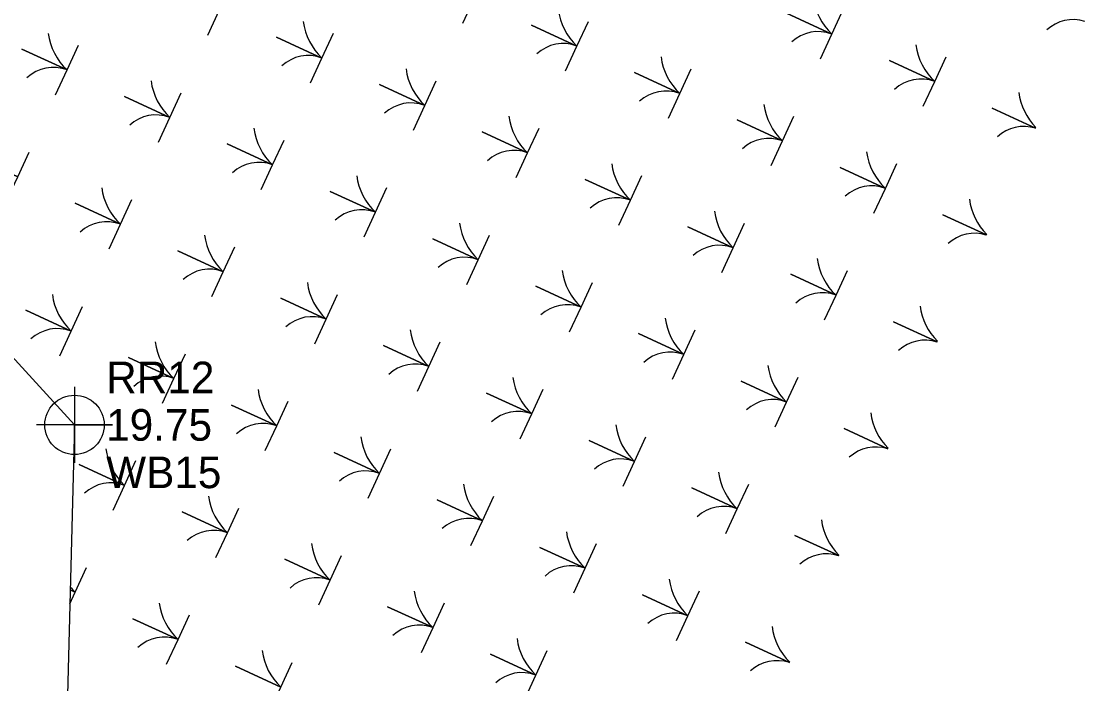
# Model space of a CAD drawing. Extents: x 2532037 to 2533565, y 713396 to 716867.
# Drawn here: x 2532898.3 to 2532982.3, y 715371.9 to 715424.3 of the extents above; entities that cross this region are included whole.
import ezdxf

# ---------------------------------------------------------------- set-up
doc = ezdxf.new("R2010")
doc.units = 0
for name, color, linetype in [('Exist Environmental Wetland Boundary', 7, 'Continuous'), ('Exist Environmental Wetland Boundary Cogo Comment', 7, 'Continuous'), ('Exist Environmental Wetland Boundary Cogo Elevation', 7, 'Continuous'), ('Exist Environmental Wetland Boundary Cogo Number', 7, 'Continuous'), ('Exist Environmental Wetland Boundary Cogo Point CELL', 7, 'Continuous'), ('Scratch_Level_1', 7, 'Continuous')]:
    doc.layers.add(name, color=color, linetype=linetype)

msp = doc.modelspace()

# ---------------------------------------------------------------- linework, layer by layer
at = {"layer": 'Exist Environmental Wetland Boundary'}
for p, q in [((2532882.006, 715414.844), (2532902.531, 715392.376)), ((2532902.531, 715392.376), (2532901.019, 715334.859))]:
    msp.add_line(p, q, dxfattribs=at)
at = {"layer": 'Exist Environmental Wetland Boundary Cogo Point CELL'}
msp.add_lwpolyline([(2532902.531, 715395.376), (2532902.531, 715389.376), (2532902.531, 715392.376), (2532905.531, 715392.376), (2532899.531, 715392.376)], dxfattribs=at)
msp.add_circle((2532902.531, 715392.376), 2.344, dxfattribs=at)
at = {"layer": 'Scratch_Level_1'}
for points in [[(2532933.199, 715424.118), (2532934.1, 715426.07), (2532930.519, 715427.724), (2532934.1, 715426.07), (2532935.002, 715428.023)], [(2532913.058, 715423.172), (2532913.959, 715425.125), (2532910.377, 715426.778), (2532913.959, 715425.125), (2532914.86, 715427.077)], [(2532961.462, 715421.314), (2532962.363, 715423.267), (2532958.781, 715424.92), (2532962.363, 715423.267), (2532963.265, 715425.219)], [(2532941.321, 715420.369), (2532942.222, 715422.321), (2532938.64, 715423.975), (2532942.222, 715422.321), (2532943.123, 715424.273)], [(2532921.179, 715419.423), (2532922.081, 715421.375), (2532918.499, 715423.029), (2532922.081, 715421.375), (2532922.982, 715423.328)], [(2532901.038, 715418.477), (2532901.939, 715420.43), (2532898.357, 715422.083), (2532901.939, 715420.43), (2532902.841, 715422.382)], [(2532969.583, 715417.565), (2532970.485, 715419.517), (2532966.903, 715421.171), (2532970.485, 715419.517), (2532971.386, 715421.47)], [(2532949.442, 715416.619), (2532950.343, 715418.572), (2532946.761, 715420.225), (2532950.343, 715418.572), (2532951.245, 715420.524)], [(2532929.301, 715415.674), (2532930.202, 715417.626), (2532926.62, 715419.28), (2532930.202, 715417.626), (2532931.103, 715419.578)], [(2532909.159, 715414.728), (2532910.061, 715416.68), (2532906.479, 715418.334), (2532910.061, 715416.68), (2532910.962, 715418.633)], [(2532978.455, 715415.838), (2532975.024, 715417.421), (2532978.455, 715415.838)], [(2532957.563, 715412.87), (2532958.465, 715414.822), (2532954.883, 715416.476), (2532958.465, 715414.822), (2532959.366, 715416.775)], [(2532937.422, 715411.924), (2532938.323, 715413.877), (2532934.742, 715415.53), (2532938.323, 715413.877), (2532939.225, 715415.829)], [(2532917.281, 715410.979), (2532918.182, 715412.931), (2532914.6, 715414.585), (2532918.182, 715412.931), (2532919.083, 715414.883)], [(2532897.139, 715410.033), (2532898.041, 715411.985), (2532894.459, 715413.639), (2532898.041, 715411.985), (2532898.942, 715413.938)], [(2532965.685, 715409.12), (2532966.586, 715411.073), (2532963.004, 715412.726), (2532966.586, 715411.073), (2532967.488, 715413.025)], [(2532945.544, 715408.175), (2532946.445, 715410.127), (2532942.863, 715411.781), (2532946.445, 715410.127), (2532947.346, 715412.08)], [(2532925.402, 715407.229), (2532926.304, 715409.182), (2532922.722, 715410.835), (2532926.304, 715409.182), (2532927.205, 715411.134)], [(2532905.261, 715406.284), (2532906.162, 715408.236), (2532902.58, 715409.89), (2532906.162, 715408.236), (2532907.064, 715410.188)], [(2532974.567, 715407.389), (2532971.126, 715408.977), (2532974.567, 715407.389)], [(2532953.665, 715404.425), (2532954.566, 715406.378), (2532950.984, 715408.031), (2532954.566, 715406.378), (2532955.468, 715408.33)], [(2532933.524, 715403.48), (2532934.425, 715405.432), (2532930.843, 715407.086), (2532934.425, 715405.432), (2532935.326, 715407.385)], [(2532913.382, 715402.534), (2532914.284, 715404.487), (2532910.702, 715406.14), (2532914.284, 715404.487), (2532915.185, 715406.439)], [(2532961.786, 715400.676), (2532962.688, 715402.628), (2532959.106, 715404.282), (2532962.688, 715402.628), (2532963.589, 715404.581)], [(2532941.645, 715399.73), (2532942.546, 715401.683), (2532938.965, 715403.336), (2532942.546, 715401.683), (2532943.448, 715403.635)], [(2532921.504, 715398.785), (2532922.405, 715400.737), (2532918.823, 715402.391), (2532922.405, 715400.737), (2532923.306, 715402.69)], [(2532901.362, 715397.839), (2532902.264, 715399.792), (2532898.682, 715401.445), (2532902.264, 715399.792), (2532903.165, 715401.744)], [(2532970.678, 715398.94), (2532967.227, 715400.533), (2532970.678, 715398.94)], [(2532949.767, 715395.981), (2532950.668, 715397.933), (2532947.086, 715399.587), (2532950.668, 715397.933), (2532951.569, 715399.886)], [(2532929.625, 715395.035), (2532930.527, 715396.988), (2532926.945, 715398.641), (2532930.527, 715396.988), (2532931.428, 715398.94)], [(2532909.484, 715394.09), (2532910.385, 715396.042), (2532906.803, 715397.696), (2532910.385, 715396.042), (2532911.287, 715397.995)], [(2532957.888, 715392.232), (2532958.789, 715394.184), (2532955.207, 715395.838), (2532958.789, 715394.184), (2532959.691, 715396.136)], [(2532937.747, 715391.286), (2532938.648, 715393.238), (2532935.066, 715394.892), (2532938.648, 715393.238), (2532939.549, 715395.191)], [(2532917.605, 715390.34), (2532918.507, 715392.293), (2532914.925, 715393.946), (2532918.507, 715392.293), (2532919.408, 715394.245)], [(2532966.79, 715390.491), (2532963.329, 715392.088), (2532966.79, 715390.491)], [(2532945.868, 715387.537), (2532946.769, 715389.489), (2532943.188, 715391.143), (2532946.769, 715389.489), (2532947.671, 715391.442)], [(2532925.727, 715386.591), (2532926.628, 715388.543), (2532923.046, 715390.197), (2532926.628, 715388.543), (2532927.529, 715390.496)], [(2532905.585, 715385.645), (2532906.487, 715387.598), (2532902.905, 715389.251), (2532906.487, 715387.598), (2532907.388, 715389.55)], [(2532953.99, 715383.787), (2532954.891, 715385.74), (2532951.309, 715387.393), (2532954.891, 715385.74), (2532955.792, 715387.692)], [(2532933.848, 715382.842), (2532934.75, 715384.794), (2532931.168, 715386.448), (2532934.75, 715384.794), (2532935.651, 715386.747)], [(2532913.707, 715381.896), (2532914.608, 715383.848), (2532911.026, 715385.502), (2532914.608, 715383.848), (2532915.51, 715385.801)], [(2532962.901, 715382.042), (2532959.43, 715383.644), (2532962.901, 715382.042)], [(2532941.97, 715379.092), (2532942.871, 715381.045), (2532939.289, 715382.698), (2532942.871, 715381.045), (2532943.772, 715382.997)], [(2532921.828, 715378.147), (2532922.73, 715380.099), (2532919.148, 715381.753), (2532922.73, 715380.099), (2532923.631, 715382.052)], [(2532902.188, 715379.338), (2532902.588, 715379.154), (2532903.49, 715381.106)], [(2532902.159, 715378.224), (2532902.588, 715379.154), (2532902.188, 715379.338)], [(2532950.091, 715375.343), (2532950.992, 715377.295), (2532947.411, 715378.949), (2532950.992, 715377.295), (2532951.894, 715379.248)], [(2532929.95, 715374.397), (2532930.851, 715376.35), (2532927.269, 715378.003), (2532930.851, 715376.35), (2532931.752, 715378.302)], [(2532909.808, 715373.452), (2532910.71, 715375.404), (2532907.128, 715377.058), (2532910.71, 715375.404), (2532911.611, 715377.357)], [(2532938.071, 715370.648), (2532938.973, 715372.6), (2532935.391, 715374.254), (2532938.973, 715372.6), (2532939.874, 715374.553)], [(2532959.012, 715373.593), (2532955.532, 715375.2), (2532959.012, 715373.593)], [(2532917.93, 715369.702), (2532918.831, 715371.655), (2532915.249, 715373.308), (2532918.831, 715371.655), (2532919.733, 715373.607)]]:
    msp.add_lwpolyline(points, dxfattribs=at)
for centre, radius, start, end in [((2532965.65, 715426.772), 4.806, 187.34643, 226.84116), ((2532945.509, 715425.826), 4.806, 187.34643, 226.84116), ((2532925.368, 715424.881), 4.806, 187.34643, 226.84116), ((2532981.421, 715421.335), 3.075, 72.678, 132.75394), ((2532905.226, 715423.935), 4.806, 187.34643, 226.84116), ((2532961.279, 715420.389), 3.075, 69.35932, 132.75394), ((2532941.138, 715419.444), 3.075, 69.35932, 132.75394), ((2532973.772, 715423.023), 4.806, 187.34643, 226.84116), ((2532920.997, 715418.498), 3.075, 69.35932, 132.75394), ((2532953.631, 715422.077), 4.806, 187.34643, 226.84116), ((2532900.855, 715417.552), 3.075, 69.35932, 132.75394), ((2532933.489, 715421.131), 4.806, 187.34643, 226.84116), ((2532913.348, 715420.186), 4.806, 187.34643, 226.84116), ((2532969.401, 715416.64), 3.075, 69.35932, 132.75394), ((2532949.26, 715415.694), 3.075, 69.35932, 132.75394), ((2532981.893, 715419.273), 4.806, 187.34643, 224.73828), ((2532929.118, 715414.749), 3.075, 69.35932, 132.75394), ((2532961.752, 715418.328), 4.806, 187.34643, 226.84116), ((2532908.977, 715413.803), 3.075, 69.35932, 132.75394), ((2532941.611, 715417.382), 4.806, 187.34643, 226.84116), ((2532921.469, 715416.436), 4.806, 187.34643, 226.84116), ((2532977.522, 715412.891), 3.075, 72.47293, 132.75394), ((2532957.381, 715411.945), 3.075, 69.35932, 132.75394), ((2532937.24, 715410.999), 3.075, 69.35932, 132.75394), ((2532969.873, 715414.578), 4.806, 187.34643, 226.84116), ((2532917.098, 715410.054), 3.075, 69.35932, 132.75394), ((2532949.732, 715413.633), 4.806, 187.34643, 226.84116), ((2532929.591, 715412.687), 4.806, 187.34643, 226.84116), ((2532909.449, 715411.741), 4.806, 187.34643, 226.84116), ((2532965.502, 715408.196), 3.075, 69.35932, 132.75394), ((2532945.361, 715407.25), 3.075, 69.35932, 132.75394), ((2532977.995, 715410.829), 4.806, 187.34643, 224.8772), ((2532925.22, 715406.304), 3.075, 69.35932, 132.75394), ((2532957.853, 715409.883), 4.806, 187.34643, 226.84116), ((2532905.078, 715405.359), 3.075, 69.35932, 132.75394), ((2532937.712, 715408.938), 4.806, 187.34643, 226.84116), ((2532917.571, 715407.992), 4.806, 187.34643, 226.84116), ((2532973.624, 715404.446), 3.075, 72.26796, 132.75394), ((2532953.482, 715403.501), 3.075, 69.35932, 132.75394), ((2532933.341, 715402.555), 3.075, 69.35932, 132.75394), ((2532965.975, 715406.134), 4.806, 187.34643, 226.84116), ((2532913.2, 715401.609), 3.075, 69.35932, 132.75394), ((2532945.834, 715405.188), 4.806, 187.34643, 226.84116), ((2532925.692, 715404.243), 4.806, 187.34643, 226.84116), ((2532905.551, 715403.297), 4.806, 187.34643, 226.84116), ((2532961.604, 715399.751), 3.075, 69.35932, 132.75394), ((2532941.463, 715398.806), 3.075, 69.35932, 132.75394), ((2532974.096, 715402.385), 4.806, 187.34643, 225.01599), ((2532921.321, 715397.86), 3.075, 69.35932, 132.75394), ((2532953.955, 715401.439), 4.806, 187.34643, 226.84116), ((2532901.18, 715396.914), 3.075, 69.35932, 132.75394), ((2532933.814, 715400.493), 4.806, 187.34643, 226.84116), ((2532913.672, 715399.548), 4.806, 187.34643, 226.84116), ((2532969.725, 715396.002), 3.075, 72.06307, 132.75394), ((2532949.584, 715395.056), 3.075, 69.35932, 132.75394), ((2532929.443, 715394.111), 3.075, 69.35932, 132.75394), ((2532962.076, 715397.69), 4.806, 187.34643, 226.84116), ((2532909.301, 715393.165), 3.075, 69.35932, 132.75394), ((2532941.935, 715396.744), 4.806, 187.34643, 226.84116), ((2532921.794, 715395.798), 4.806, 187.34643, 226.84116), ((2532957.705, 715391.307), 3.075, 69.35932, 132.75394), ((2532937.564, 715390.361), 3.075, 69.35932, 132.75394), ((2532970.198, 715393.94), 4.806, 187.34643, 225.15466), ((2532917.423, 715389.416), 3.075, 69.35932, 132.75394), ((2532950.057, 715392.995), 4.806, 187.34643, 226.84116), ((2532929.915, 715392.049), 4.806, 187.34643, 226.84116), ((2532909.774, 715391.103), 4.806, 187.34643, 226.84116), ((2532965.827, 715387.557), 3.075, 71.85827, 132.75394), ((2532945.686, 715386.612), 3.075, 69.35932, 132.75394), ((2532925.544, 715385.666), 3.075, 69.35932, 132.75394), ((2532958.178, 715389.245), 4.806, 187.34643, 226.84116), ((2532905.403, 715384.721), 3.075, 69.35932, 132.75394), ((2532938.037, 715388.3), 4.806, 187.34643, 226.84116), ((2532917.895, 715387.354), 4.806, 187.34643, 226.84116), ((2532953.807, 715382.863), 3.075, 69.35932, 132.75394), ((2532933.666, 715381.917), 3.075, 69.35932, 132.75394), ((2532966.299, 715385.496), 4.806, 187.34643, 225.29321), ((2532913.524, 715380.971), 3.075, 69.35932, 132.75394), ((2532946.158, 715384.55), 4.806, 187.34643, 226.84116), ((2532926.017, 715383.605), 4.806, 187.34643, 226.84116), ((2532961.928, 715379.113), 3.075, 71.65355, 132.75394), ((2532941.787, 715378.168), 3.075, 69.35932, 132.75394), ((2532921.646, 715377.222), 3.075, 69.35932, 132.75394), ((2532905.875, 715382.659), 4.806, 220.004, 226.84116), ((2532954.28, 715380.801), 4.806, 187.34643, 226.84116), ((2532901.504, 715376.276), 3.075, 69.35932, 77.18234), ((2532934.138, 715379.855), 4.806, 187.34643, 226.84116), ((2532913.997, 715378.91), 4.806, 187.34643, 226.84116), ((2532949.909, 715374.418), 3.075, 69.35932, 132.75394), ((2532929.767, 715373.473), 3.075, 69.35932, 132.75394), ((2532962.401, 715377.052), 4.806, 187.34643, 225.43164), ((2532909.626, 715372.527), 3.075, 69.35932, 132.75394), ((2532942.26, 715376.106), 4.806, 187.34643, 226.84116), ((2532922.118, 715375.16), 4.806, 187.34643, 226.84116), ((2532958.03, 715370.669), 3.075, 71.44892, 132.75394), ((2532937.889, 715369.723), 3.075, 69.35932, 132.75394)]:
    msp.add_arc(centre, radius, start, end, dxfattribs=at)

# ---------------------------------------------------------------- texts
at = {"layer": 'Exist Environmental Wetland Boundary Cogo Comment'}
msp.add_text('WB15', height=2.5, dxfattribs=at).set_placement((2532905.031, 715387.376))
at = {"layer": 'Exist Environmental Wetland Boundary Cogo Elevation'}
msp.add_text('19.75', height=2.5, dxfattribs=at).set_placement((2532905.031, 715391.126))
at = {"layer": 'Exist Environmental Wetland Boundary Cogo Number'}
msp.add_text('RR12', height=2.5, dxfattribs=at).set_placement((2532905.031, 715394.876))

doc.saveas('drawing.dxf')
